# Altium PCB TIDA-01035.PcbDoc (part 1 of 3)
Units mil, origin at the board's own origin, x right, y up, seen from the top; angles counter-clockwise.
Board outline 3937.01 x 2952.76 mil, 4 copper layers (Top Layer, GND, PWR, Bottom Layer), stack 79.834 mil thick; 286 components, 165 nets, 861 pads, 352 vias.
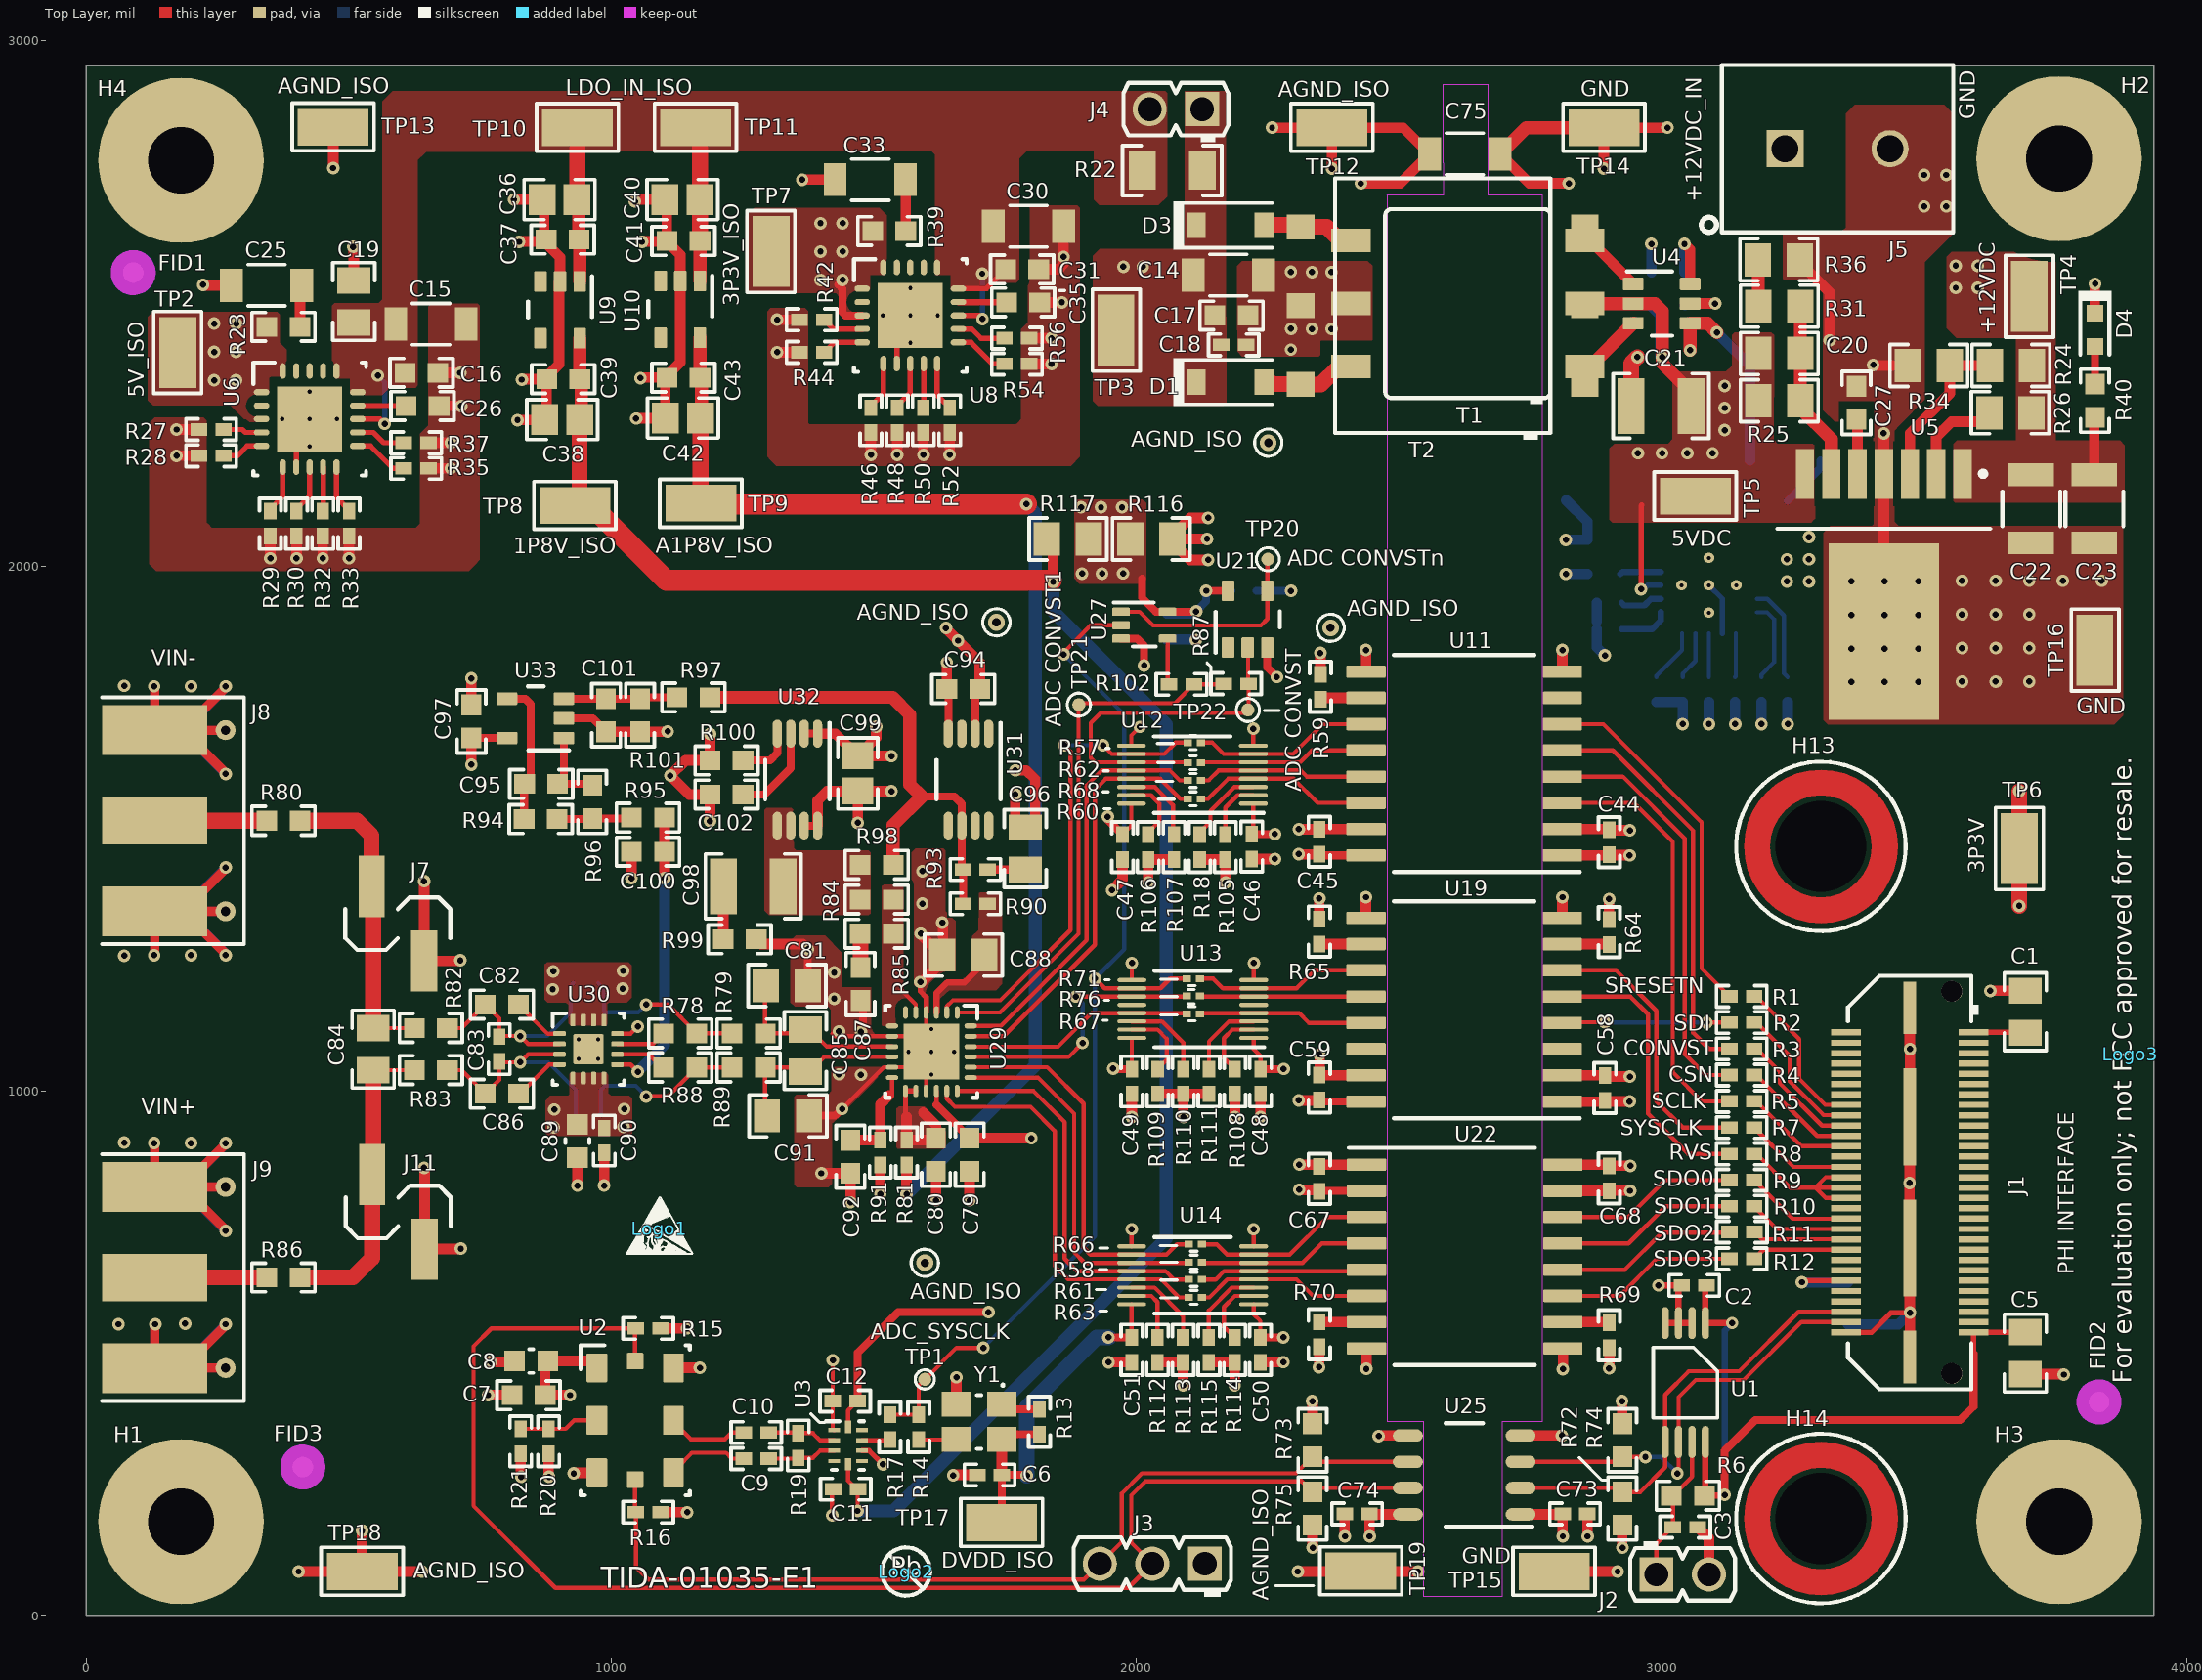
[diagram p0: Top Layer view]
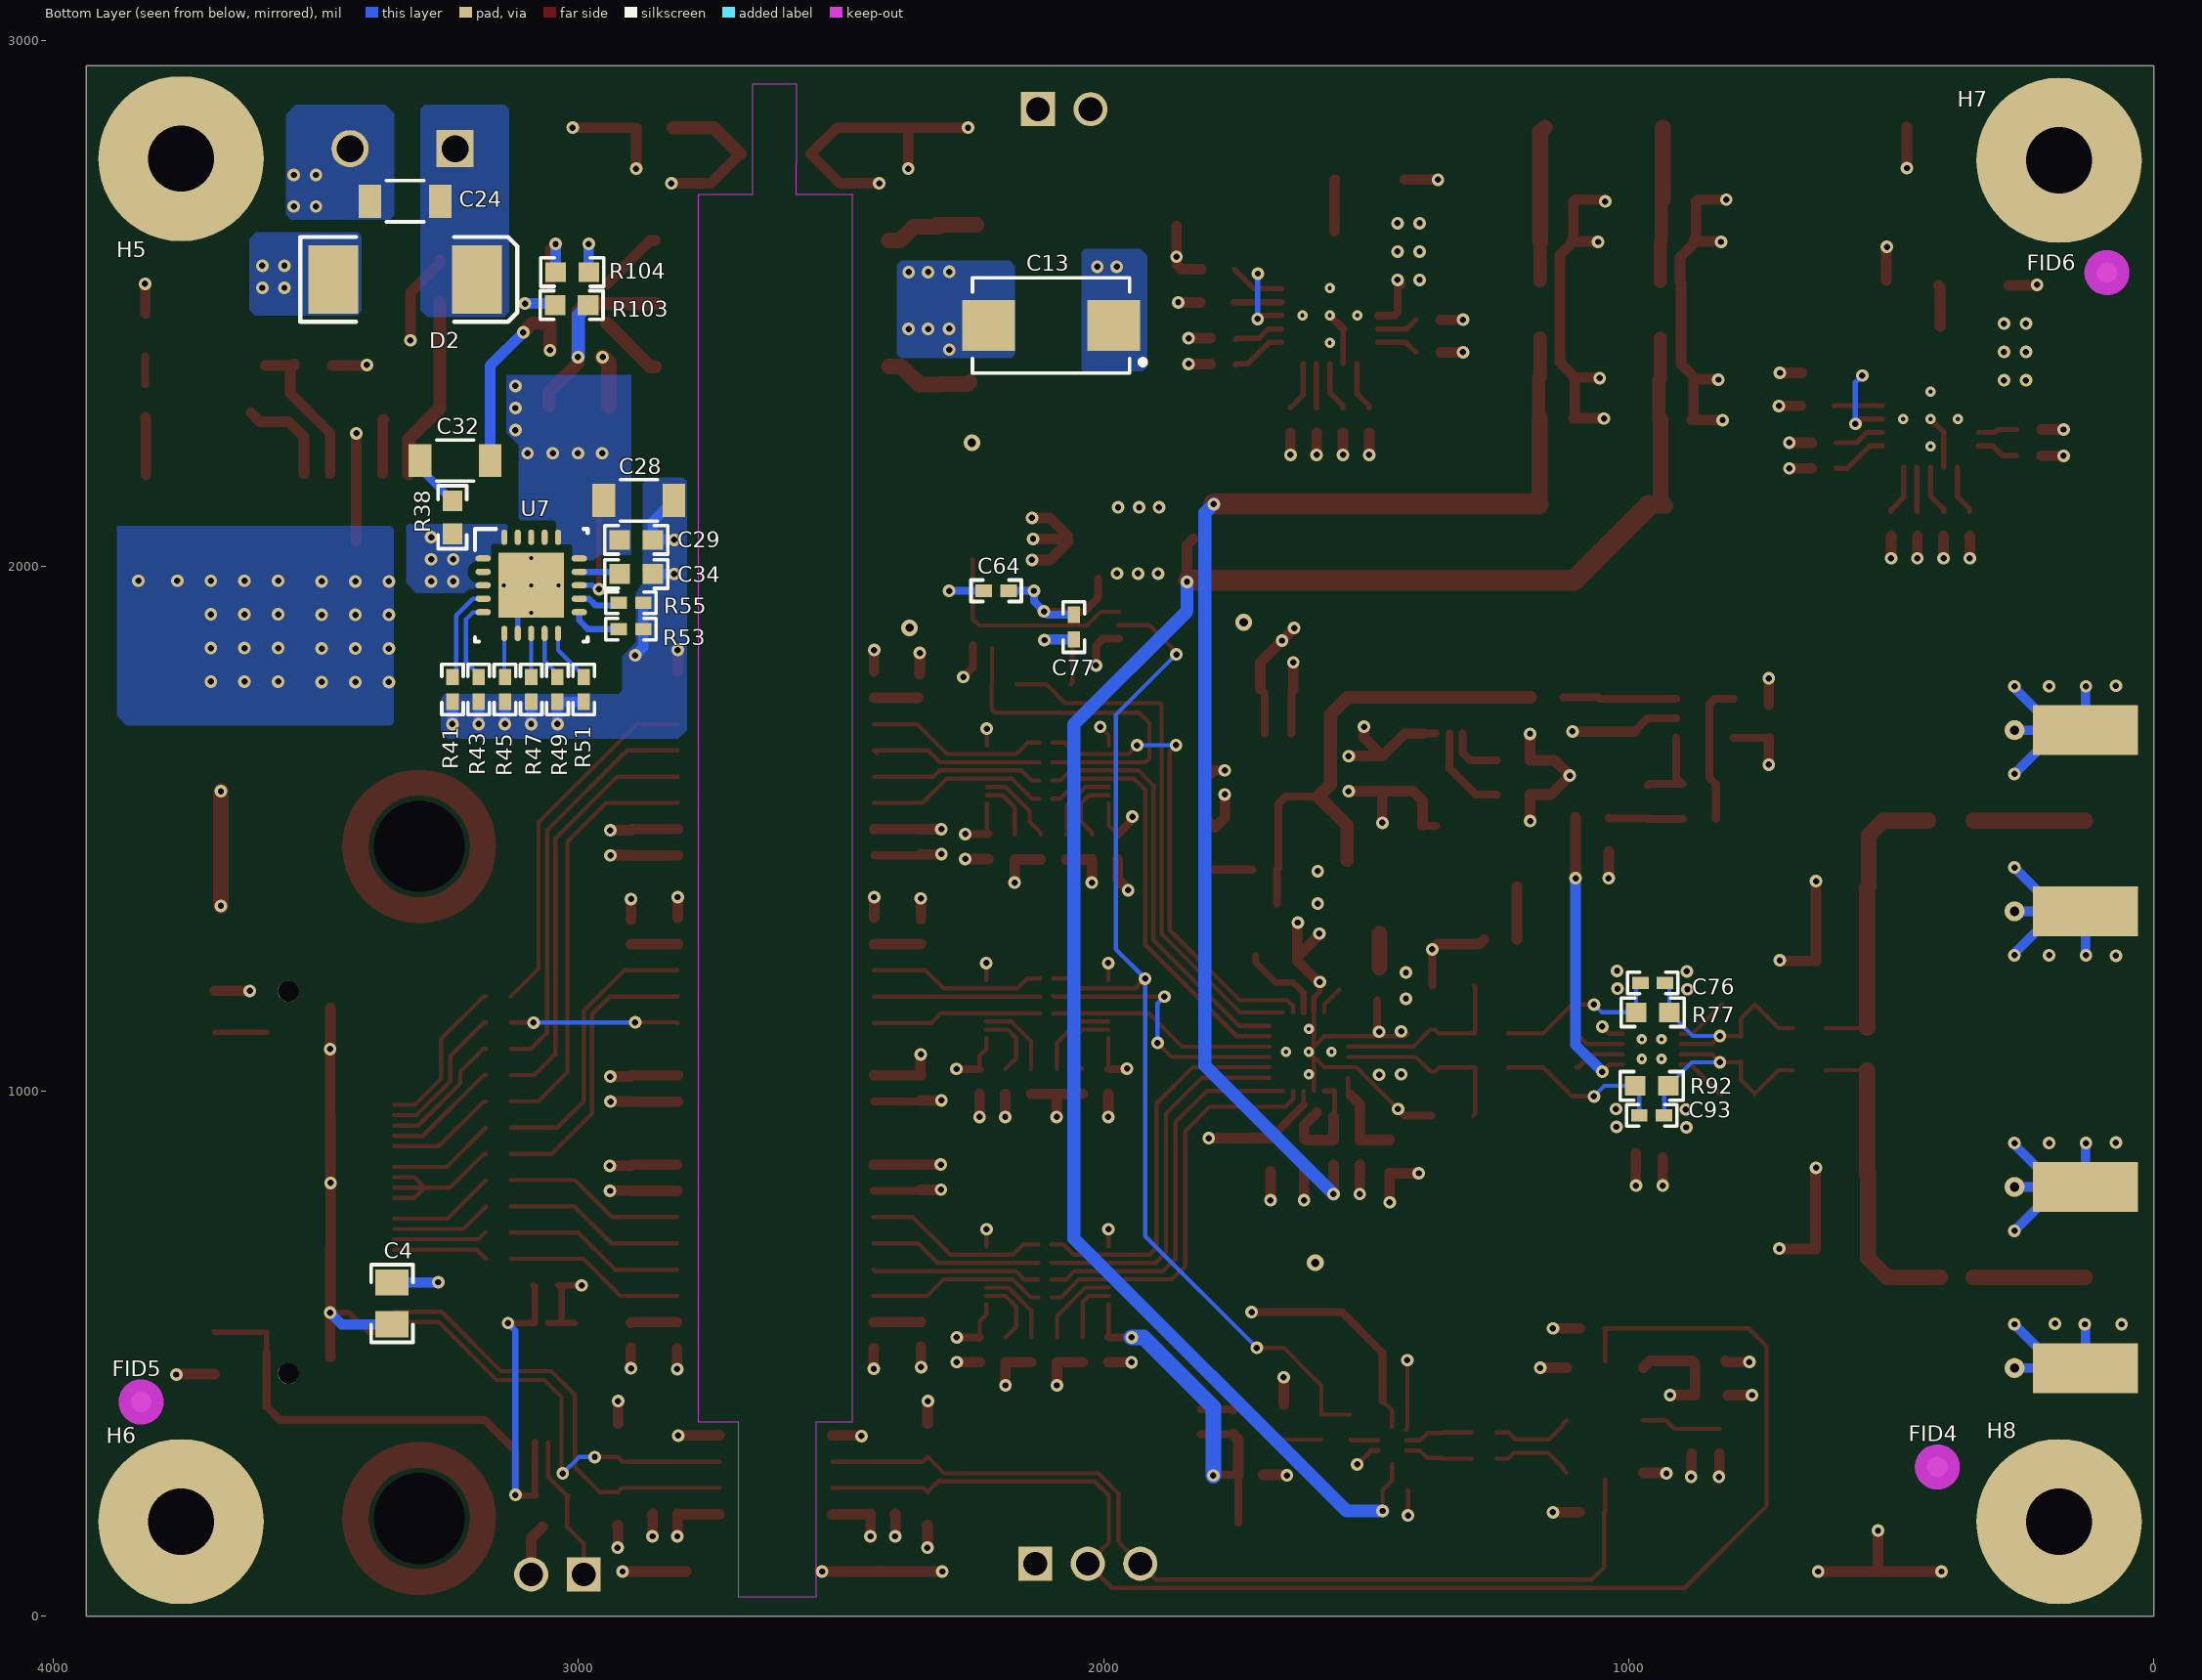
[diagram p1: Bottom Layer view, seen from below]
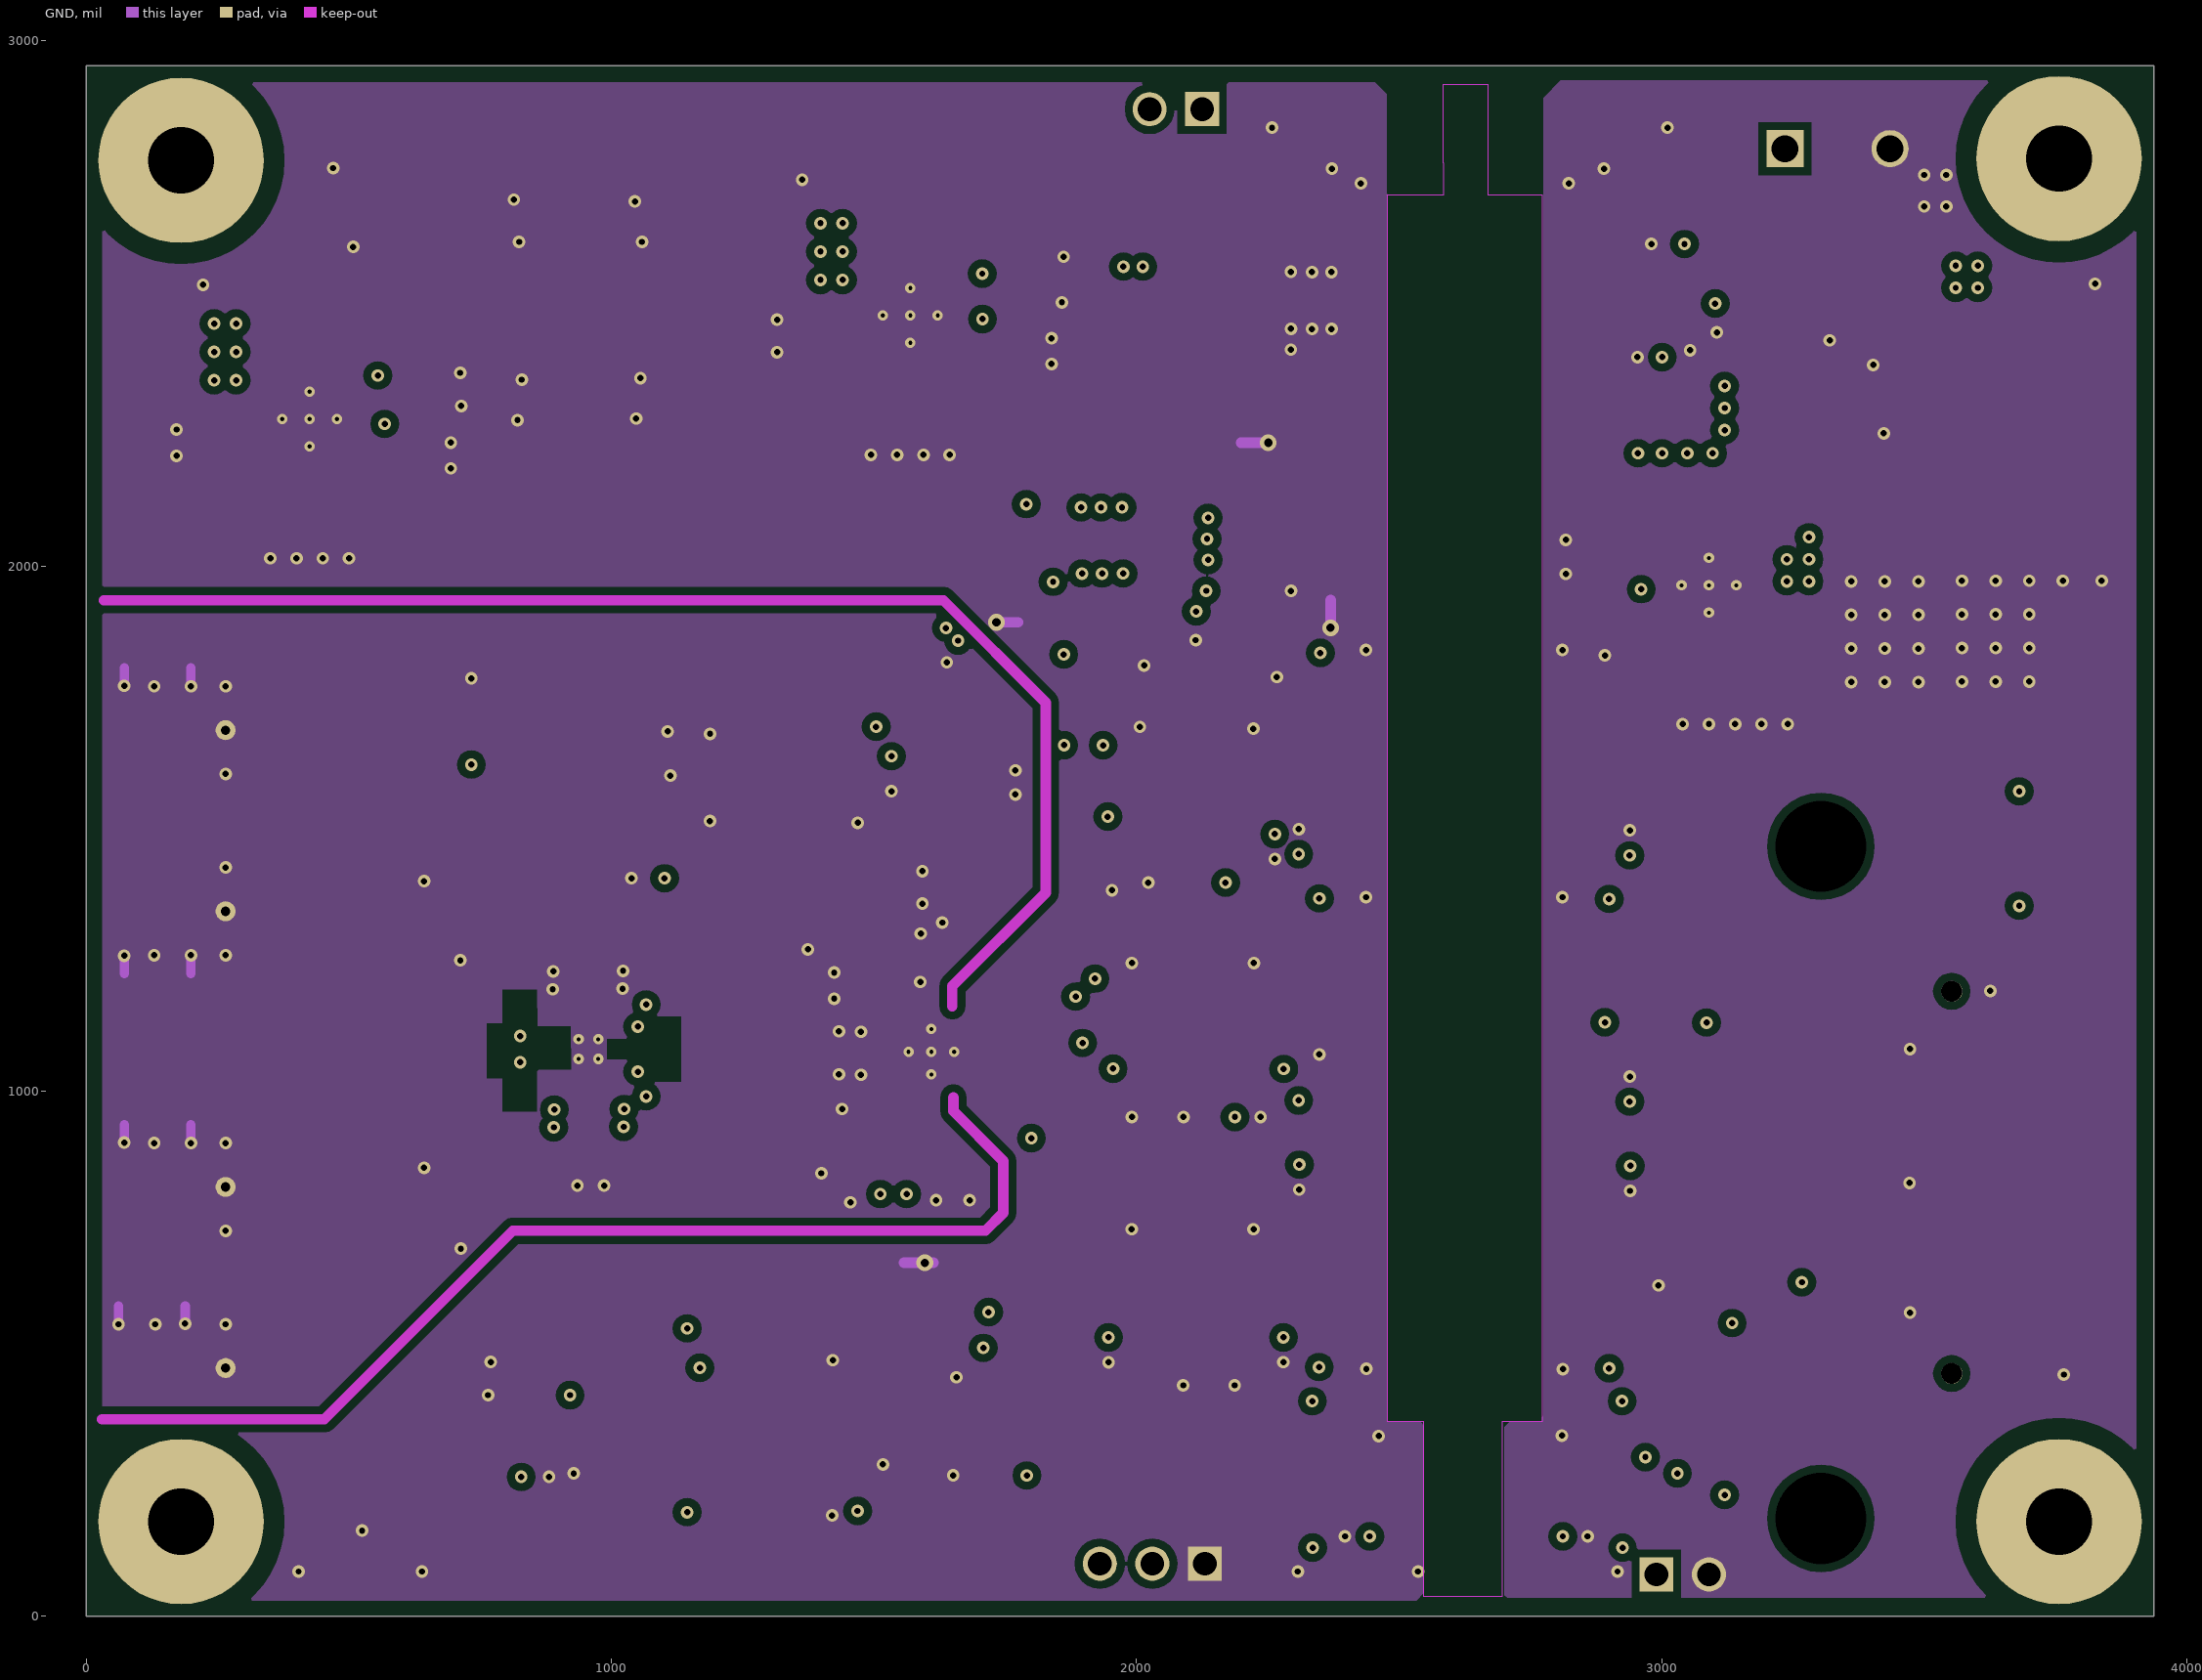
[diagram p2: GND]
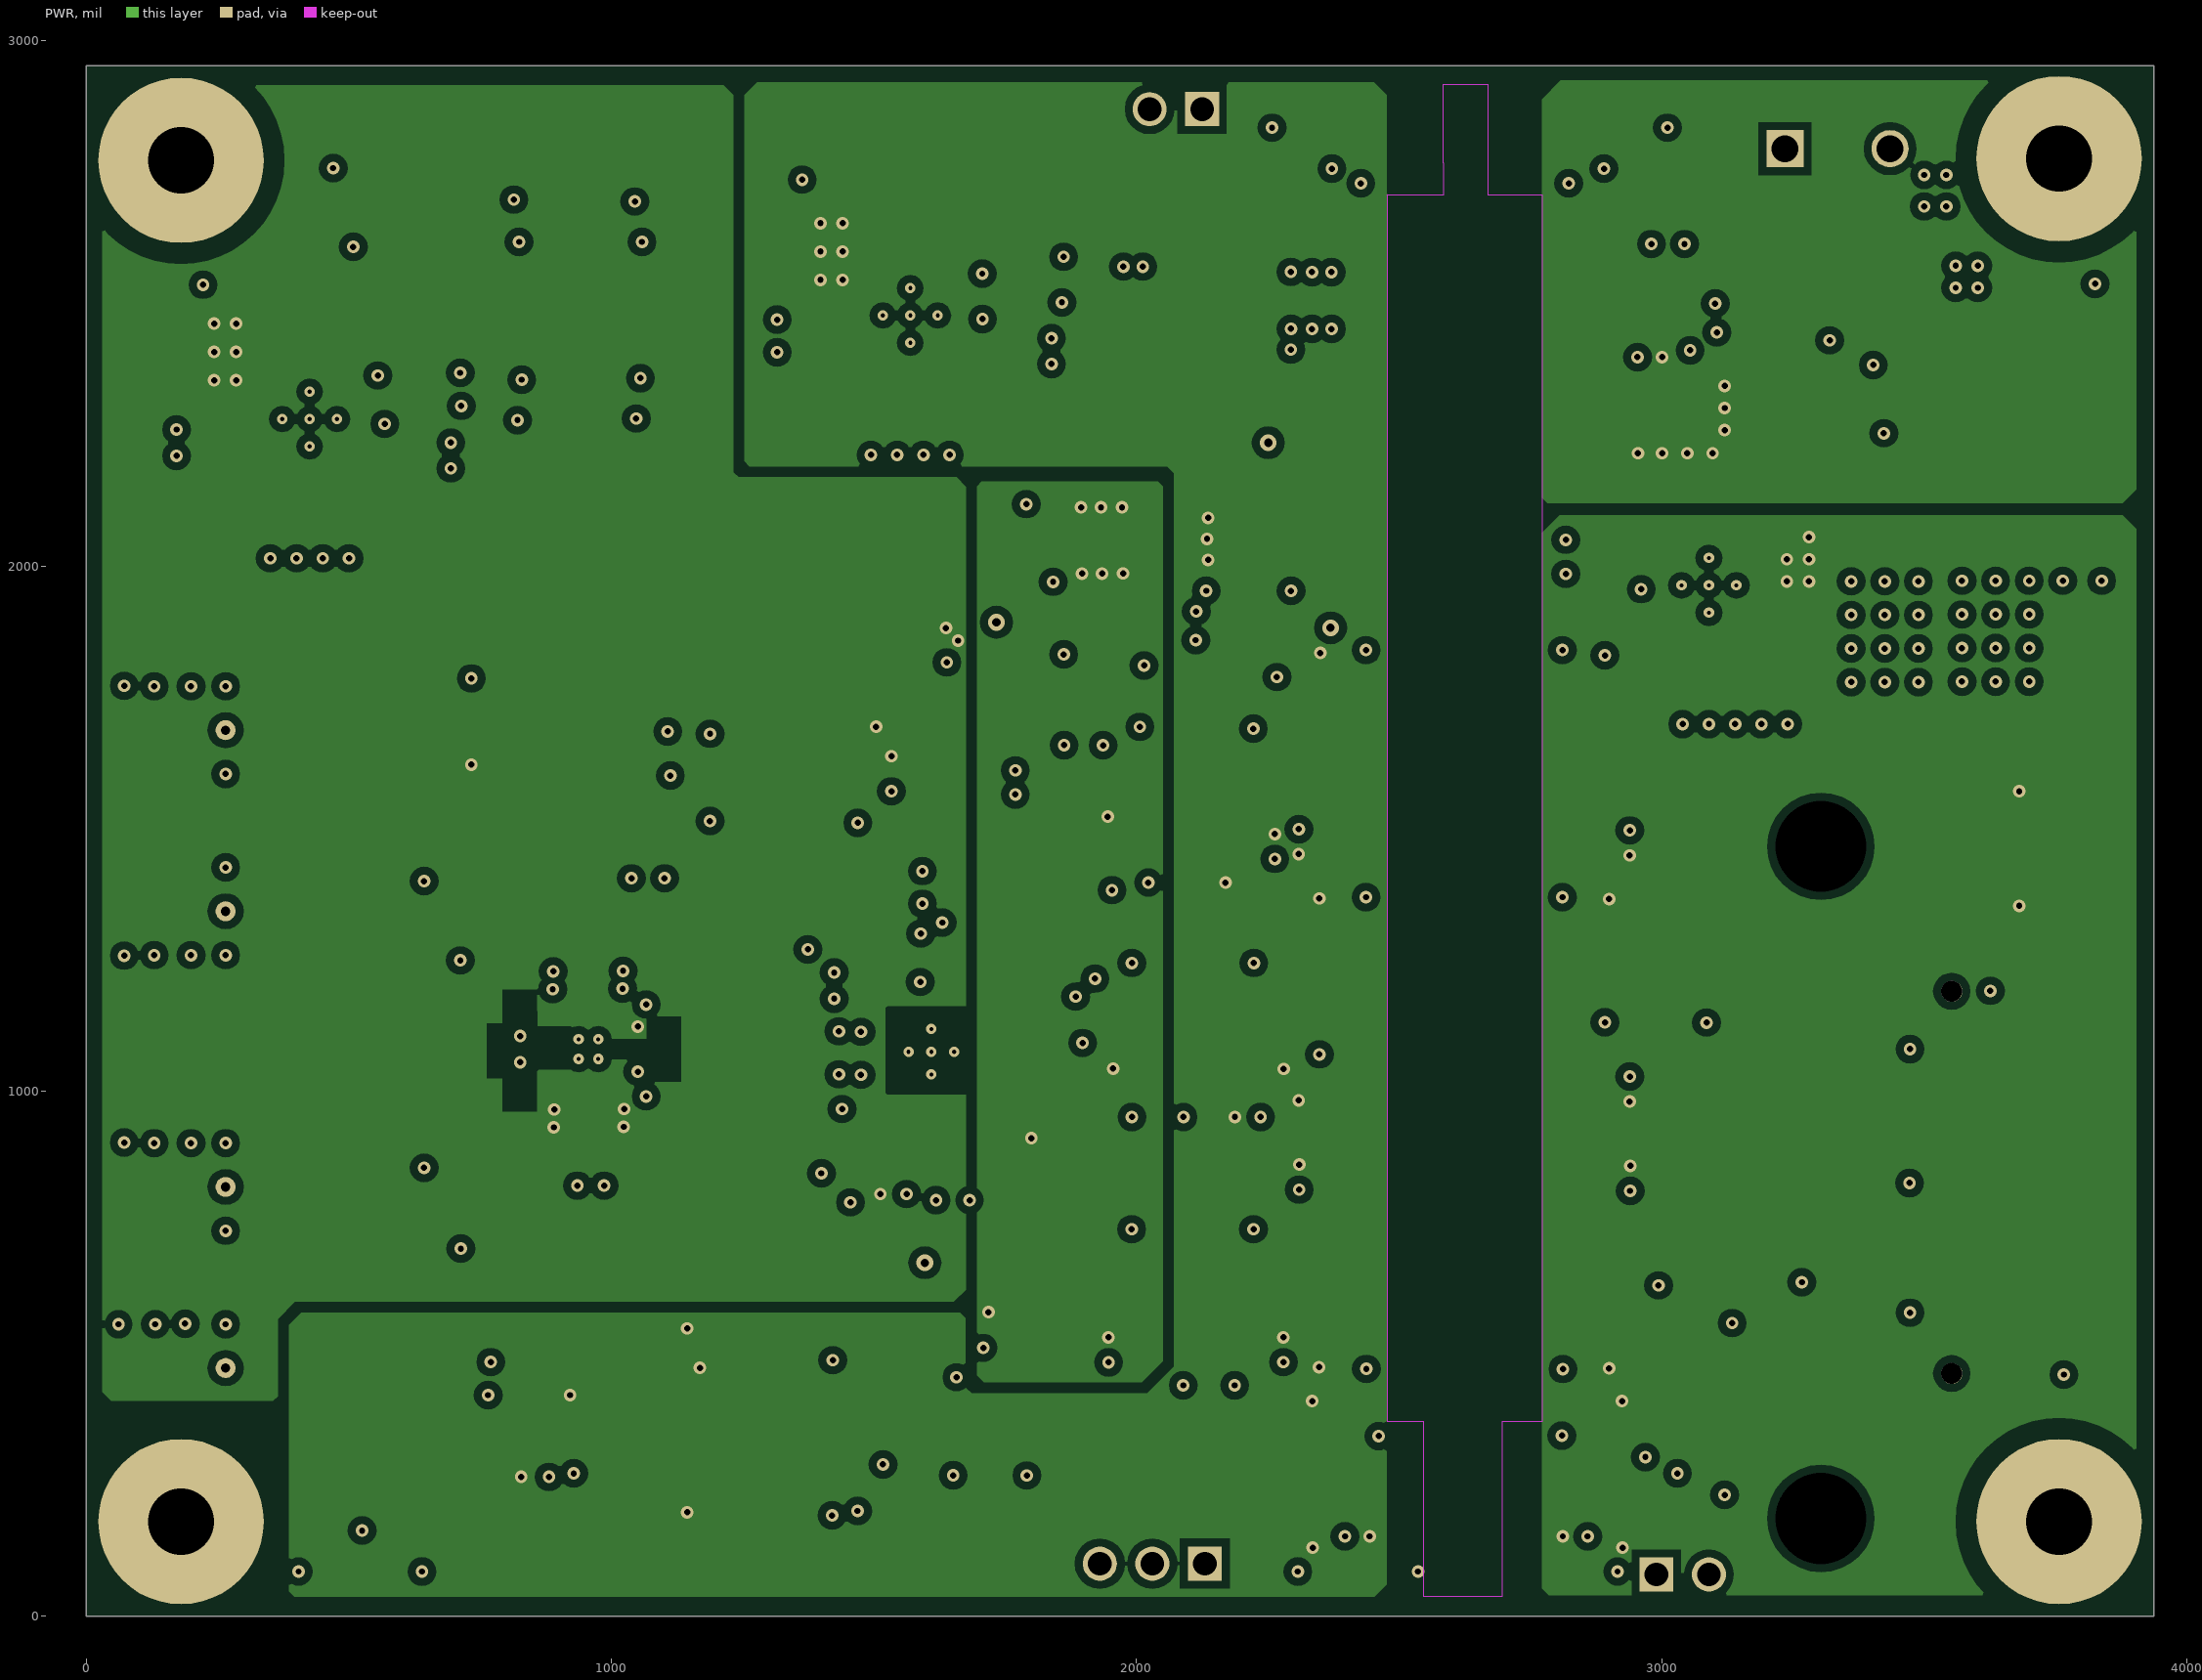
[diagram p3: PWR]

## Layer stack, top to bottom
Top Solder: solder mask 0.4, Solder Resist, Dk 3.5
Top Layer: signal copper 1.4
Dielectric1: core 59.2, FR-4, Dk 4.8
GND: signal copper 1.417
Dielectric 3: prepreg 5, Dk 4.2
PWR: signal copper 1.417
Dielectric 2: core 10, Dk 4.2
Bottom Layer: signal copper 1.4
Bottom Solder: solder mask 0.4, Solder Resist, Dk 3.5

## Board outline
0,0 0,2952.76 3937.01,2952.76 3937.01,0

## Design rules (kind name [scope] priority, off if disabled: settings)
AcuteAngle [All] p1: minimum=4.50000000000000E+0001 checktracksonly=FALSE
AssemblyTestPointUsage [All] p1: valid=2
Clearance Clearance_MTG_COPPER [InPadClass('MTG') vs InPoly] p1: gap=40
Clearance "Shape to Shape" [InPolygon vs InPolygon] p2: gap=20
Clearance "shape to all" [InPolygon] p3: gap=15
Clearance Clearance_Boardedge_poly [OnCopper and InPolygon vs IsKeepOut] p4: gap=20
Clearance Clearance_u [InPadClass('U31')] p5: gap=7.7
Clearance "Clearance_via_thr pin" [IsVia vs IsThruPin] p6: gap=8
Clearance "SMD to Via" [IsSMTPin vs IsVia] p7: gap=8
Clearance [All] p8: gap=7.5
DiffPairsRouting DiffPair_DiffPairsRouting [InDifferentialPair ('kan')] p1: maxlimit=16 minlimit=16 mostfreqgap=16 toplayer_minwidth=8 toplayer_maxwidth=8 toplayer_prefwidth=8 midlayer1_minwidth=8 midlayer1_maxwidth=8 midlayer1_prefwidth=8 midlayer2_minwidth=8 midlayer2_maxwidth=8 midlayer2_prefwidth=8 bottomlayer_minwidth=8 bottomlayer_maxwidth=8 bottomlayer_prefwidth=8 maxuncoupledlength=500
DiffPairsRouting [All] p2: maxlimit=16 minlimit=16 mostfreqgap=16 toplayer_minwidth=8 toplayer_maxwidth=8 toplayer_prefwidth=8 midlayer1_minwidth=8 midlayer1_maxwidth=8 midlayer1_prefwidth=8 midlayer2_minwidth=8 midlayer2_maxwidth=8 midlayer2_prefwidth=8 bottomlayer_minwidth=8 bottomlayer_maxwidth=8 bottomlayer_prefwidth=8 maxuncoupledlength=1000
FabricationTestPointUsage TestPointUsage [All] p1: valid=2 allowmultiple=FALSE
FabricationTestpoint Testpoint [All] p1: side=3 testpointundercomponent=TRUE minsize=40 maxsize=100 preferedsize=60 minholesize=0 maxholesize=40 preferedholesize=32 testpointgrid=1 allowsidetop=TRUE allowsidebottom=TRUE usegrid=TRUE gridtolerance=0.01
FanoutControl Fanout_LCC [IsLCC] p1: bgadir=Out bgaviamode=Centered fanoutstyle=Auto fanoutdirection=Alternating viagrid=1 // Fanout_LCC (Default Rule)
FanoutControl Fanout_BGA [IsBGA] p2: bgadir=Out bgaviamode=Centered fanoutstyle=Auto fanoutdirection=Alternating viagrid=1 // Fanout_BGA (Default Rule)
FanoutControl Fanout_Default [All] p4: bgadir=Out bgaviamode=Centered fanoutstyle=Auto fanoutdirection=Alternating viagrid=1 // Fanout_Default (Default Rule)
FanoutControl Fanout_Small [(CompPinCount < 5)] p5: bgadir=Out bgaviamode=Centered fanoutstyle=Auto fanoutdirection=OutThenIn viagrid=1 // Fanout_Small (Default Rule)
HoleSize [All] p1: absolutevalues=TRUE maxlimit=251 minlimit=7 maxpercent=80.000 minpercent=20.000
MatchedLengths DiffPair_MatchedLengths [InDifferentialPair ('kan')] p1: tolerance=1000 checknetsindiffpair=TRUE checkdiffpairvsdiffpair=FALSE checkxsignals=FALSE checkothers=FALSE
MatchedLengths DiffPair_MatchedLengths_1 [InDifferentialPair ('kan')] p2: tolerance=1000 checknetsindiffpair=TRUE checkdiffpairvsdiffpair=FALSE checkxsignals=FALSE checkothers=FALSE
MinimumAnnularRing [All] p1: minimumring=5
MinimumAnnularRing MinimumAnnularRing_ThermalPadVias [IsVia and InAnyComponent] p2: minimumring=5.91
MinimumSolderMaskSliver MinimumSolderMaskSliver_Logo [InComponentClass('Logo') vs InComponentClass('Logo')] p1: minsoldermaskwidth=0.7
MinimumSolderMaskSliver [All] p2: minsoldermaskwidth=3.94
PlaneClearance [All] p1: clearance=15
PlaneConnect [All] p1: planeconnectstyle=Direct reliefexpansion=10 reliefentries=4 reliefconductorwidth=10 reliefairgap=10
PolygonConnect [All] p1: connectstyle=Direct reliefconductorwidth=10 reliefentries=4 polygonreliefangle="90 Angle" airgapwidth=10
RoutingVias RoutingVias_power [InNetClass('POWER')] p1: holewidth=16 width=32 viastyle="Through Hole" minholewidth=7.87 minwidth=19.68 maxholewidth=16 maxwidth=32
RoutingVias ThermalPadVias [IsVia and InAnyComponent] p2: holewidth=8 width=20 viastyle="Through Hole" minholewidth=7.87 minwidth=19 maxholewidth=12 maxwidth=24
RoutingVias [All] p3: holewidth=12 width=24 viastyle="Through Hole" minholewidth=7.87 minwidth=19.68 maxholewidth=16 maxwidth=32
SMDToCorner [All] p1: distance=30000
SilkToSilkClearance [All] p1: silktosilkclearance=5
SilkToSolderMaskClearance SilkscreenOverComponentPads [IsPad] p1: minsilkscreentomaskgap=5 clearancetoexposedcopper=TRUE
SolderMaskExpansion [All] p1: expansion=3
Width Width_power [InNetClass('pwr')] p1: maxlimit=200 minlimit=8 preferedwidth=20
Width [All] p2: maxlimit=100 minlimit=6 preferedwidth=8 checkconnectedcopper=TRUE
16 further rules are at their usual default settings.

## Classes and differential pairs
component class "Mounting Holes": H1 H2 H3 H4
pad class MTG: H1-1 H2-1 H3-1 H4-1 H5-0 H6-0 H7-0 H8-0
component class Header: J2 J3 J4 J7 J11
component class AssemblyNote: ZZ1 ZZ2 ZZ3
pad class U31: J1-1 J1-2 J1-3 J1-4 J1-5 J1-6 J1-7 J1-8 J1-9 J1-10 J1-11 J1-12 J1-13 J1-14 J1-15 J1-16 J1-17 J1-18 J1-19 J1-20 J1-21 J1-22 J1-23 J1-24 J1-25 J1-26 J1-27 J1-28 J1-29 J1-30 J1-31 J1-32 J1-33 J1-34 J1-35 J1-36 J1-37 J1-38 J1-39 J1-40 J1-41 J1-42 J1-43 J1-44 J1-45 J1-46 J1-47 J1-48 J1-49 J1-50 J1-51 J1-52 J1-53 J1-54 J1-55 J1-56 J1-57 J1-58 J1-59 J1-60 J1-MH1 J1-MH2 J1-MP1 J1-MP2 J1-MP3 J1-MP4 U13-1 U13-2 U13-3 U13-4 U13-5 U13-6 U13-7 U13-8 U13-9 U13-10 U13-11 U13-12 U13-13 U13-14 U13-15 U13-16 U14-1 U14-2 U14-3 U14-4 U14-5 U14-6 U14-7 U14-8 U14-9 U14-10 U14-11 U14-12 U14-13 U14-14 U14-15 U14-16 U31-1 U31-2 U31-3 U31-4 U31-5 U31-6 U31-7 U31-8 U32-2 U32-3 U32-4 U32-5 U32-6 U32-7 U32-8 U33-1 U33-2 U33-3 U33-4 U33-5
component class TIDA-01035_Hardware: FID1 FID2 FID3 FID4 FID5 FID6 H1 H2 H3 H4 H5 H6 H7 H8 H13 H14 Logo1 Logo2 Logo3 ZZ1 ZZ2 ZZ3
component class FiducialMark: FID1 FID2 FID3 FID4 FID5 FID6
component class TIDA-01035_ADC1: C64 C76 C77 C79 C80 C81 C82 C83 C84 C85 C86 C87 C88 C89 C90 C91 C92 C93 C94 C95 C96 C97 C98 C99 C100 C101 C102 J7 J8 J9 J11 R77 R78 R79 R80 R81 R82 R83 R84 R85 R86 R87 R88 R89 R90 R91 R92 R93 R94 R95 R96 R97 R98 R99 R100 R101 R102 R116 R117 TP20 TP21 TP22 U21 U27 U29 U30 U31 U32 U33
component class TIDA-01035_CONNECTOR: C1 C2 C3 C4 C5 C6 C7 C8 C9 C10 C11 C12 J1 J2 J3 R1 R2 R3 R4 R5 R6 R7 R8 R9 R10 R11 R12 R13 R14 R15 R16 R17 R19 R20 R21 TP1 U1 U2 U3 Y1
component class TIDA-01035_DATA_ISOLATION: C44 C45 C46 C47 C48 C49 C50 C51 C58 C59 C67 C68 C73 C74 C75 R18 R57 R58 R59 R60 R61 R62 R63 R64 R65 R66 R67 R68 R69 R70 R71 R72 R73 R74 R75 R76 R105 R106 R107 R108 R109 R110 R111 R112 R113 R114 R115 TP12 TP13 TP14 TP15 TP16 TP17 TP18 TP19 U11 U12 U13 U14 U19 U22 U25
component class TIDA-01035_POWER_ISOLATION: C13 C14 C15 C16 C17 C18 C19 C20 C21 C22 C23 C24 C25 C26 C27 C28 C29 C30 C31 C32 C33 C34 C35 C36 C37 C38 C39 C40 C41 C42 C43 D1 D2 D3 D4 J4 J5 R22 R23 R24 R25 R26 R27 R28 R29 R30 R31 R32 R33 R34 R35 R36 R37 R38 R39 R40 R41 R42 R43 R44 R45 R46 R47 R48 R49 R50 R51 R52 R53 R54 R55 R56 R103 R104 T1 T2 TP2 TP3 TP4 TP5 TP6 TP7 TP8 TP9 TP10 TP11 U4 U5 U6 U7 U8 U9 U10
differential pair BCLK: +BCLK_P -BCLK_N

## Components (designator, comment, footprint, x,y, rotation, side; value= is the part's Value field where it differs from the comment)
C1 "GRM21BR71A106KE51L" 0805_HV 3692.5,1151.05 r90 top
C2 "GRM155R71C104KA88D" 0402 3062,630 r0 top
C3 "GRM155R71C104KA88D" 0402 3045,169.5 r180 top
C4 "GRM21BR71A106KE51L" 0805_HV 3355,595.62 r270 bottom
C5 "GRM21BR71A106KE51L" 0805_HV 3692.5,501.05 r270 top
C6 "GRM155R71C104KA88D" 0402 1720,269 r180 top
C7 "C0603C104J3RACTU" 0603 842,421 r180 top
C8 "ZRB18AD71A106KE01L" 0603_120 847,486 r180 top
C9 "GRM155R61E104KA87D" 0402 1275.51,300 r0 top
C10 "GRM155R61E104KA87D" 0402 1275.51,350 r0 top
C11 "GRM155R71C104KA88D" 0402 1446,242 r180 top
C12 "GRM155R71C104KA88D" 0402 1445,410 r180 top
C13 "TPME107K020R0035" 7343-43 2099.79,2458.35 r0 bottom
C14 "C3216X7R1E106M160AE" 1206_190 2174.79,2554.35 r0 top
C15 "C3216X5R1E476M160AC" 1206_190 656.07,2460.86 r0 top
C16 "GRM1885C1H102FA01J" 0603 638.06,2368.06 r0 top
C17 "GRM188R71E105KA12D" 0603 2180.79,2477.35 r0 top
C18 "GRM155R71C104KA88D" 0402 2184.79,2421.35 r180 top
C19 "GRM21BR71A106KE51L" 0805_HV 509,2504 r90 top
C20 "08055C223KAT2A" 0805_HV 3224,2405 r0 top
C21 "C3225X5R1A226M230AA" 1210 2999,2305 r180 top
C22 "C1210C106K5RACTU" 1210_280 3704,2109 r270 top
C23 "C1210C106K5RACTU" 1210_280 3824,2109 r270 top
C24 "C3216X7R1E106M160AE" 1206_190 3330,2695 r0 bottom
C25 "C3216X5R1E476M160AC" 1206_190 343.07,2534.86 r180 top
C26 "GRM188R71E105KA12D" 0603 640.06,2305.06 r180 top
C27 "C0603C103J5RACTU" 0603 3371,2311 r90 top
C28 "C3216X5R1E476M160AC" 1206_190 2885,2125 r180 bottom
C29 "GRM1885C1H102FA01J" 0603 2890,2050 r180 bottom
C30 "C3216X5R1E476M160AC" 1206_190 1794,2647.27 r0 top
C31 "GRM1885C1H102FA01J" 0603 1782,2565.27 r0 top
C32 "C3216X5R1E476M160AC" 1206_190 3235,2201 r180 bottom
C33 "C3216X5R1E476M160AC" 1206_190 1493,2736 r180 top
C34 "GRM188R71E105KA12D" 0603 2890,1985 r0 bottom
C35 "GRM188R71E105KA12D" 0603 1784,2502.27 r180 top
C36 "08055C105KAT2A" 0805 901,2698 r180 top
C37 "C0603C104K5RACTU" 0603 907,2622 r180 top
C38 "0805YD106MAT2A" 0805 906,2279 r180 top
C39 "C0603C104K5RACTU" 0603 908,2356 r180 top
C40 "08055C105KAT2A" 0805 1135,2698 r180 top
C41 "C0603C104K5RACTU" 0603 1137,2619 r180 top
C42 "0805YD106MAT2A" 0805 1136,2282 r180 top
C43 "C0603C104K5RACTU" 0603 1137,2359 r180 top
C44 "GRM155R71C104KA88D" 0402 2900,1474 r270 top
C45 "GRM155R71C104KA88D" 0402 2348,1475 r90 top
C46 "GRM155R71C104KA88D" 0402 2219.18,1465.77 r270 top
C47 "GRM155R71C104KA88D" 0402 1973.18,1464.77 r270 top
C48 "GRM155R71C104KA88D" 0402 2236.04,1018.4 r270 top
C49 "GRM155R71C104KA88D" 0402 1991.04,1018.4 r270 top
C50 "GRM155R71C104KA88D" 0402 2235.68,507.27 r270 top
C51 "GRM155R71C104KA88D" 0402 1990.68,507.27 r270 top
C58 "GRM155R71C104KA88D" 0402 2892,1006 r270 top
C59 "GRM155R71C104KA88D" 0402 2348,1007 r90 top
C64 "GRM155R71C104KA88D" 0402 2204.58,1952.91 r180 bottom
C67 "GRM155R71C104KA88D" 0402 2348,833 r90 top
C68 "GRM155R71C104KA88D" 0402 2900,834 r270 top
C73 "GRM155R71C104KA88D" 0402 2835,195 r180 top
C74 "GRM155R71C104KA88D" 0402 2420,195 r180 top
C75 "202R18W102KV4E" 1206_190 2625,2785 r0 top
C76 "885012005061" 0402 954,1206 r180 bottom
C77 "GRM155R71C104KA88D" 0402 2056.58,1883.91 r90 bottom
C79 "GRM188R71E105KA12D" 0603 1682,879 r90 top
C80 "GRM188R71E105KA12D" 0603 1618,879 r270 top
C81 "GRM2165C2A471JA01D" 0805_HV 1334,1201 r0 top
C82 "GRM1885C1H102FA01J" 0603 791,1165 r180 top
C83 "885012005061" 0402 786,1080 r270 top
C84 "C0805C103F1GACTU" 0805_HV 546,1080 r90 top
C85 "C0805C102J1GACTU" 0805_HV 1369,1077 r270 top
C86 "GRM1885C1H102FA01J" 0603 791,995 r180 top
C87 "GRM188R60J226MEA0J" 0603 1474,1204 r270 top
C88 "GRM21BR71A106KE51L" 0805_HV 1670,1259 r180 top
C89 "ZRB18AD71A106KE01L" 0603_120 935,905 r270 top
C90 "GRM155R71C104KA88D" 0402 986,906 r90 top
C91 "GRM2165C2A471JA01D" 0805_HV 1336,953 r0 top
C92 "GRM188R71E105KA12D" 0603 1455,875 r270 top
C93 "885012005061" 0402 956,954 r180 bottom
C94 "GRM188R71E105KA12D" 0603 1670,1766 r180 top
C95 "GRM188R71E105KA12D" 0603 866,1585 r180 top
C96 "GRM21BR71A106KE51L" 0805_HV 1788,1462 r90 top
C97 "C0603C104J3RACTU" 0603 733,1704 r270 top
C98 "GRM32ER71A476KE15L" 1210 1270,1390 r0 top
C99 "GRM21BR71A106KE51L" 0805 1469,1605 r90 top
C100 "GRM188R71E105KA12D" 0603 1069.5,1456 r180 top
C101 "GRM188R71E105KA12D" 0603 989.5,1716 r270 top
C102 "GRM188R71A105KA61D" 0603 1219.06,1564.94 r180 top
D1 "MBR0520LT1G" SOD-123 2178,2350.35 r0 top
D2 "MBRS4201T3G" SMC 3330,2546 r180 bottom
D3 "MBR0520LT1G" SOD-123 2178,2649 r0 top
D4 "150060RS75000" WL-SMCW_RED 3825,2450 r270 top
FID1 "Fiducial" Fiducial10-20 89,2559 r180 top
FID2 "Fiducial" Fiducial10-20 3833,408 r180 top
FID3 "Fiducial" Fiducial10-20 412,284 r180 top
FID4 "Fiducial" Fiducial10-20 412,284 r0 bottom
FID5 "Fiducial" Fiducial10-20 3833,408 r0 bottom
FID6 "Fiducial" Fiducial10-20 89,2559 r0 bottom
H1 "9330" "NY PMS 440 0025 PH" 180,180 r0 top
H2 "9330" "NY PMS 440 0025 PH" 3757.01,2775.91 r0 top
H3 "9330" "NY PMS 440 0025 PH" 3757.01,180 r0 top
H4 "9330" "NY PMS 440 0025 PH" 180,2772.76 r0 top
H5 "1902C" Keystone_1902C 3757.01,2775.91 r180 bottom
H6 "1902C" Keystone_1902C 3757.01,180 r180 bottom
H7 "1902C" Keystone_1902C 180,2772.76 r180 bottom
H8 "1902C" Keystone_1902C 180,180 r180 bottom
H13 "9774050360R" Wurth_WA-SMSI 3303.24,1466.05 r0 top locked
H14 "9774050360R" Wurth_WA-SMSI 3303.24,186.05 r0 top locked
J1 "QTH-030-03-L-D-A" SAMTEC_QTH-030-01-X-D-A 3472.5,826.05 r270 top
J2 "61300211121" WURTH_61300211121 3040,79.5 r0 top
J3 "61300311121" WURTH_61300311121 2030,100 r180 top
J4 "61300211121" WURTH_61300211121 2074.79,2870.35 r180 top
J5 "8718" 691213510002 3335,2795 r0 top
J7 "0878980204" Molex_87898-0204 593,1319 r180 top
J8 "142-0701-801" JOHNSON_142-0701-801#1 130,1515 r90 top locked
J9 "142-0701-801" JOHNSON_142-0701-801#2 130,645 r90 top locked
J11 "0878980204" Molex_87898-0204 594,770 r180 top
Logo1 "ESD Susceptible" ESD_Overlay_small 1091,738 r0 top
Logo2 "Pb-Free Symbol" Pb-Free_Overlay_Small 1561,85 r0 top
Logo3 "FCC disclaimer" FCC_disclaimer 3893,1070 r90 top
R1 "ERJ-2GE0R00X" 0402 3152.5,1180.55 r0 top
R2 "ERJ-2GE0R00X" 0402 3152.5,1130.55 r0 top
R3 "ERJ-2GE0R00X" 0402 3152.5,1080.55 r0 top
R4 "ERJ-2GE0R00X" 0402 3152.5,1030.55 r0 top
R5 "ERJ-2GE0R00X" 0402 3152.5,980.55 r0 top
R6 "CRCW060310K0FKEA" 0603 3050,229.5 r0 top
R7 "ERJ-2GE0R00X" 0402 3152.5,930.55 r0 top
R8 "ERJ-2GE0R00X" 0402 3152.5,880.55 r0 top
R9 "ERJ-2GE0R00X" 0402 3152.5,830.55 r0 top
R10 "ERJ-2GE0R00X" 0402 3152.5,780.55 r0 top
R11 "ERJ-2GE0R00X" 0402 3153,732 r0 top
R12 "ERJ-2GE0R00X" 0402 3152.5,680.55 r0 top
R13 "CRCW040233R0JNED" 0402 1815,370 r270 top
R14 "CRCW040233R0JNED" 0402 1585,360 r90 top
R15 "CRCW04024K70JNED" 0402 1070,548 r0 top
R16 "CRCW04024K70JNED" 0402 1070,198 r0 top
R17 "CRCW040233R0JNED" 0402 1530,360 r90 top
R18 "ERJ-2RKF1002X" 0402 2120.18,1464.77 r270 top
R19 "RC0402FR-07100RL" 0402 1355.51,325 r270 top
R20 "CRCW04024K70JNED" 0402 880,333 r90 top
R21 "CRCW04024K70JNED" 0402 827,333 r90 top
R22 "CRCW12060000Z0EA" 1206 2067.79,2753.35 r180 top
R23 "ERJ-3RSFR10V" 0603 375.07,2455.86 r180 top
R24 "ERJ-6ENF1183V" 0805_HV 3665,2382 r0 top
R25 "RC0805FR-075K62L" 0805_HV 3224,2315 r180 top
R26 "CRCW0805249KFKEA" 0805_HV 3664,2292 r0 top
R27 "ERJ-2GE0R00X" 0402 237.44,2260.06 r0 top
R28 "ERJ-2GE0R00X" 0402 237.44,2210.06 r0 top
R29 "ERJ-2GE0R00X" 0402 350.06,2080.68 r90 top
R30 "ERJ-2GE0R00X" 0402 400.06,2080.68 r90 top
R31 "RR1220P-5490-D-M" 0805_HV 3224,2495 r0 top
R32 "ERJ-2GE0R00X" 0402 450.06,2080.68 r90 top
R33 "ERJ-2GE0R00X" 0402 500.06,2080.68 r90 top
R34 "CRCW080520K5FKEA" 0805_HV 3509,2382 r0 top
R35 "ERJ-2GE0R00X" 0402 628.06,2186.06 r180 top
R36 "RR1220P-3920-D-M" 0805_HV 3223.21,2583.35 r180 top
R37 "ERJ-2GE0R00X" 0402 628.06,2235.06 r180 top
R38 "ERJ-3RSFR10V" 0603 3240,2093 r270 bottom
R39 "ERJ-3RSFR10V" 0603 1529,2638 r180 top
R40 "CRCW06031K20JNEA" 0603 3825,2315 r270 top
R41 "ERJ-2GE0R00X" 0402 3240,1765 r90 bottom
R42 "ERJ-2GE0R00X" 0402 1381.38,2469.27 r0 top
R43 "ERJ-2GE0R00X" 0402 3190,1765 r90 bottom
R44 "ERJ-2GE0R00X" 0402 1381.38,2407.27 r0 top
R45 "ERJ-2GE0R00X" 0402 3140,1765 r90 bottom
R46 "ERJ-2GE0R00X" 0402 1494,2277.89 r90 top
R47 "ERJ-2GE0R00X" 0402 3090,1765 r90 bottom
R48 "ERJ-2GE0R00X" 0402 1544,2277.89 r90 top
R49 "ERJ-2GE0R00X" 0402 3040,1765 r90 bottom
R50 "ERJ-2GE0R00X" 0402 1594,2277.89 r90 top
R51 "ERJ-2GE0R00X" 0402 2990,1765 r90 bottom
R52 "ERJ-2GE0R00X" 0402 1644,2277.89 r90 top
R53 "ERJ-2GE0R00X" 0402 2900,1880 r0 bottom
R54 "ERJ-2GE0R00X" 0402 1772,2385 r180 top
R55 "ERJ-2GE0R00X" 0402 2900,1930 r0 bottom
R56 "ERJ-2GE0R00X" 0402 1772,2434 r180 top
R57 "ERJ-1GN0R00C" 0201 2110.18,1663.77 r180 top
R58 "ERJ-1GN0R00C" 0201 2111.68,674.27 r180 top
R59 "ERJ-2RKF1002X" 0402 2350,1770 r90 top
R60 "ERJ-1GN0R00C" 0201 2110.18,1556.77 r180 top
R61 "ERJ-1GN0R00C" 0201 2111.68,641.27 r180 top
R62 "ERJ-1GN0R00C" 0201 2110.18,1625.77 r180 top
R63 "ERJ-1GN0R00C" 0201 2111.68,607.27 r180 top
R64 "ERJ-2RKF1002X" 0402 2900,1303 r270 top
R65 "ERJ-2RKF1002X" 0402 2348,1304 r90 top
R66 "ERJ-1GN0R00C" 0201 2111.68,708.27 r180 top
R67 "ERJ-1GN0R00C" 0201 2108.04,1147.4 r180 top
R68 "ERJ-1GN0R00C" 0201 2110.18,1591.77 r180 top
R69 "ERJ-2RKF1002X" 0402 2900,535 r270 top
R70 "ERJ-2RKF1002X" 0402 2348,537 r90 top
R71 "ERJ-1GN0R00C" 0201 2108.04,1214.4 r180 top
R72 "CRCW06031K50JNEA" 0603 2925,205 r270 top
R73 "CRCW06031K50JNEA" 0603 2335,335 r90 top
R74 "CRCW06031K50JNEA" 0603 2925,335 r90 top
R75 "CRCW06031K50JNEA" 0603 2335,205 r270 top
R76 "ERJ-1GN0R00C" 0201 2108.04,1181.4 r180 top
R77 "RG1608P-102-B-T5" 0603 954,1150 r0 bottom
R78 "CRCW06030000Z0EA" 0603 1131,1110 r0 top
R79 "RR0816Q-22R1-D-34R" 0603 1261,1110 r0 top
R80 "ERJ-3GEY0R00V" 0603 375,1515 r0 top locked
R81 "ERJ-2GE0R00X" 0402 1562,883 r90 top
R82 "RG1608P-102-B-T5" 0603 656,1120 r0 top
R83 "RG1608P-102-B-T5" 0603 656,1040 r0 top
R84 "CRCW06030000Z0EA" 0603 1505,1365 r180 top
R85 "CRCW06031R00FKEA" 0603 1505,1300 r0 top
R86 "ERJ-3GEY0R00V" 0603 375,645 r0 top locked
R87 "ERJ-2GE0R00X" 0402 2189.58,1775.91 r0 top
R88 "CRCW06030000Z0EA" 0603 1131,1045 r0 top
R89 "RR0816Q-22R1-D-34R" 0603 1261,1045 r0 top
R90 "ERJ-2RKF1002X" 0402 1693,1357 r0 top
R91 "ERJ-2GE0R00X" 0402 1512,883 r270 top
R92 "RG1608P-102-B-T5" 0603 956,1010 r0 bottom
R93 "ERJ-2BQFR22X" 0402 1693,1422 r180 top
R94 "RG1608P-203-B-T5" 0603 865,1518 r0 top
R95 "CRCW06031K00FKEA" 0603 1069.5,1521 r180 top
R96 "RG1608P-4990-B-T5" 0603 963,1551 r270 top
R97 "RG1608P-4992-B-T5" 0603 1156,1750 r0 top
R98 "CRCW06030000Z0EA" 0603 1505,1431 r180 top
R99 "ERJ-3RQFR22V" 0603 1244,1289 r0 top
R100 "ERJ-3RQFR22V" 0603 1219.06,1629.94 r0 top
R101 "RG1608P-4992-B-T5" 0603 1054.5,1716 r90 top
R102 "ERJ-2GE0R00X" 0402 2085.58,1774.91 r180 top
R103 "CRCW06030000Z0EA" 0603 3013,2497 r180 bottom
R104 "CRCW06030000Z0EA" 0603 3012,2560 r0 bottom
R105 "ERJ-2RKF1002X" 0402 2169.18,1464.77 r270 top
R106 "ERJ-2RKF1002X" 0402 2022.18,1464.77 r90 top
R107 "ERJ-2RKF1002X" 0402 2071.18,1464.77 r90 top
R108 "ERJ-2RKF1002X" 0402 2187.04,1018.4 r270 top
R109 "ERJ-2RKF1002X" 0402 2040.04,1018.4 r90 top
R110 "ERJ-2RKF1002X" 0402 2089.04,1018.4 r90 top
R111 "ERJ-2RKF1002X" 0402 2138.04,1018.4 r90 top
R112 "ERJ-2RKF1002X" 0402 2039.68,507.27 r90 top
R113 "ERJ-2RKF1002X" 0402 2088.68,507.27 r90 top
R114 "ERJ-2RKF1002X" 0402 2186.68,507.27 r90 top
R115 "ERJ-2RKF1002X" 0402 2137.68,507.27 r90 top
R116 "CRCW08050000Z0EA" 0805_HV 2028.18,2051.77 r0 top
R117 "CRCW08050000Z0EA" 0805_HV 1869.18,2051.77 r180 top
T1 "750313734" Wurth_750313638 2631,2500 r180 top
T2 "750315240" Wurth_750315240 2583,2496 r180 top
TP1 "TP-025-SMT" TP_25MIL-SMT 1596.64,451 r0 top
TP2 "5015" Testpoint_Keystone_Miniature 174.07,2406.86 r270 top
TP3 "5015" Testpoint_Keystone_Miniature 1960.79,2449.35 r90 top
TP4 "5015" Testpoint_Keystone_Miniature 3700,2514 r90 top
TP5 "5015" Testpoint_Keystone_Miniature 3064,2133 r180 top
TP6 "5015" Testpoint_Keystone_Miniature 3681,1462 r90 top
TP7 "5015" Testpoint_Keystone_Miniature 1304,2599 r270 top
TP8 "5015" Testpoint_Keystone_Miniature 930,2115 r180 top
TP9 "5015" Testpoint_Keystone_Miniature 1170,2120 r0 top
TP10 "5015" Testpoint_Keystone_Miniature 935,2835 r180 top
TP11 "5015" Testpoint_Keystone_Miniature 1160,2835 r180 top
TP12 "5015" Testpoint_Keystone_Miniature 2372,2835 r180 top
TP13 "5015" Testpoint_Keystone_Miniature 470,2836 r180 top
TP14 "5015" Testpoint_Keystone_Miniature 2890,2835 r180 top
TP15 "5015" Testpoint_Keystone_Miniature 2795,85 r180 top
TP16 "5015" Testpoint_Keystone_Miniature 3825,1840 r90 top
TP17 "5015" Testpoint_Keystone_Miniature 1743,178 r180 top
TP18 "5015" Testpoint_Keystone_Miniature 525,85 r180 top
TP19 "5015" Testpoint_Keystone_Miniature 2427,86 r180 top
TP20 "TP-025-SMT" TP_25MIL-SMT 2250,2013 r90 top
TP21 "TP-025-SMT" TP_25MIL-SMT 1890,1736 r90 top
TP22 "TP-025-SMT" TP_25MIL-SMT 2212,1726 r90 top locked
U1 "BR24G32FVT-3AGE2" TSOP65P640X120-8N 3045,445 r270 top
U2 "LMK61E2-SIAT" SIA0008B 1045,373 r0 top
U3 "SN65LVDS4RSET" RSE0010A 1450.51,325 r0 top
U4 "SN6505ADBVR" DBV0006A_N 3000,2500 r0 top
U5 "LMZ14203TZ-ADJ/NOPB" TZA07A_V 3423,1965 r270 top
U6 "TPS7A4700RGWR" RGW0020A 425.06,2280.06 r0 top
U7 "TPS7A4700RGWR" RGW0020A 3090,1963.35 r180 bottom
U8 "TPS7A4700RGWR" RGW0020A 1569,2477.27 r0 top
U9 "TPS70918DBVT" DBV0005A_N 902,2488 r270 top
U10 "TPS70918DBVT" DBV0005A_N 1131,2489 r270 top
U11 "ISO7840DW" DW0016B_N 2624,1624 r180 top
U12 "SN74AVC4T245DGVR" DGV0016A_N 2106.18,1602.77 r180 top
U13 "SN74AVC4T245DGVR" DGV0016A_N 2107.04,1156.4 r180 top
U14 "SN74AVC4T245DGVR" DGV0016A_N 2106.68,649.27 r180 top
U19 "ISO7842DWR" DW0016B_N 2624,1155 r180 top
U21 "SN74AHC1G04DBVR" DBV0005A_N 2211.58,1898.91 r90 top
U22 "ISO7840DW" DW0016B_N 2625,685 r0 top
U25 "ISO1541DR" D0008A_N 2624,269 r180 top
U27 "SN74AUP1G80DCKR" DCK0005A_N 2014.71,1887.41 r0 top
U29 "ADS8900BIRGER" RGE0024H 1609.06,1074.94 r270 top
U30 "THS4551IRGTR" RGT0016A 956,1080 r0 top
U31 "REF5050AIDGKT" DGK0008A_N 1679.85,1593.28 r270 top
U32 "REF6041AIDGK" DGK0008A_N 1354.06,1593.28 r270 top
U33 "OPA376AIDBVR" DBV0005A_N 855,1710 r180 top
Y1 "ASTMLPE-125.000MHZ-LJ-E-T" TXC_AU 1700,370 r270 top
ZZ1 "These assemblies are ESD sensitive, ESD precautions shall be observed." AssemblyNote 1803.9,6136.61 r0 top
ZZ2 "These assemblies must be clean and free from flux and all contaminants. Use of no clean flux is not acceptable." AssemblyNote 1803.9,6051.61 r0 top
ZZ3 "These assemblies must comply with workmanship standards IPC-A-610 Class 2, unless otherwise specified." AssemblyNote 1803.9,5976.61 r0 top

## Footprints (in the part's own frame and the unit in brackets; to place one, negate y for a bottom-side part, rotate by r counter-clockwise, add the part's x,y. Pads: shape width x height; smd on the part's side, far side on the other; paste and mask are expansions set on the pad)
0201 [mil]
  rect 16x13 smd: 1(-12.5,0) 2(12.5,0)
0402 [mm] "0402 from SM-752 data"
  rect 0.8x0.6 smd: 1(-0.6,0) 2(0.6,0)
  silkscreen extent -1.22,-0.52 1.22,0.52, body extent -0.55,-0.3 0.55,0.3, height 0.6
0603 [mm] "0603 from SM-752 data"
  rect 1x0.95 smd: 1(-0.8,0) 2(0.8,0)
  silkscreen extent -1.52,-0.69 1.52,0.69, body extent -0.87,-0.47 0.87,0.47, height 1
0603_120 [mm] "0603_120"
  rect 1x1 smd: 1(-0.8,0) 2(0.8,0)
  silkscreen extent -0.1,-0.58 0.1,0.58, body extent -0.87,-0.48 0.87,0.48, height 1.2
0805 [mm] "0805 from SM-752 data"
  rect 1.3x1.5 smd: 1(-0.85,0) 2(0.85,0)
  silkscreen extent -1.72,-0.97 1.72,0.97, body extent -1.1,-0.72 1.1,0.72, height 1.45
0805_HV [mil] "0805 with 30mil clearance between pads"
  rect 50x63 smd: 1(-40,0) 2(40,0)
  silkscreen extent -74,-40 74,40, body extent -43,-29 43,29, height 57
1206 [mm] "1206 from SM-752 data"
  rect 1.3x1.85 smd: 1(-1.45,0) 2(1.45,0)
  silkscreen extent -2.4,-1.21 2.4,1.21, body extent -1.7,-0.9 1.7,0.9, height 1.35
1206_190 [mm] "1206_190"
  rect 1.1x1.6 smd: 1(-1.7,0) 2(1.7,0)
  silkscreen extent -0.9,-1 0.9,1, body extent -1.75,-0.95 1.75,0.95, height 1.9
1210 [mm] "1210 from SM-752 data"
  rect 1.3x2.7 smd: 1(-1.45,0) 2(1.45,0)
  silkscreen extent -2.32,-1.57 2.32,1.57, body extent -1.7,-1.35 1.7,1.35, height 1.35
1210_280 [mm] "SMD, 2-Leads, Body 3.6x2.8mm, Height 2.8mm"
  rect 1.1x2.2 smd: 1(-1.65,0) 2(1.65,0)
  silkscreen extent -0.84,-1.4 0.84,1.4, body extent -1.8,-1.4 1.8,1.4, height 2.8
7343-43 [mm] "Medium density IPC based on Kemet T495 series"
  rect 2.55x2.45 smd: 1(-3.025,0) 2(3.025,0)
  silkscreen extent -4.56,-2.3 3.8,2.3, body extent -3.8,-2.3 3.8,2.3, height 4.3
691213510002 [mm] "Serie 2135 - 5.08 mm _ 2 pins"
  rect 1.8x1.8 hole 1.3: 1(-2.54,0)
  round 1.8 hole 1.3: 2(2.54,0)
  silkscreen extent -5.6,-4.05 5.6,4.05, body extent -5.68,-4 5.68,4.1, height 10.1
AssemblyNote [mil] "Assembly Note"
D0008A_N [mm] "SOIC, 8-Leads, Body 4.9x3.9mm, Pitch 1.27mm, IPC Medium Density"
  oval 1.45x0.6 smd: 1(-2.725,1.905) 2(-2.725,0.635) 3(-2.725,-0.635) 4(-2.725,-1.905) 5(2.725,-1.905) 6(2.725,-0.635) 7(2.725,0.635) 8(2.725,1.905)
  silkscreen extent -3.3,-2.5 0.9,2.5, body extent -3,-2.45 3,2.45, height 1.63
DBV0005A_N [mm]
  rrect17% 1x0.6 smd: 1(-1.375,0.95) 2(-1.375,0) 3(-1.375,-0.95) 4(1.375,-0.95) 5(1.375,0.95)
  silkscreen extent -1.63,-1.55 0.38,1.55, body extent -1.42,-1.46 1.42,1.46, height 1.09
DBV0006A_N [mm] "SOT23, 6-Leads, Body 2.9x1.6mm, Pitch 0.95mm, Lead Span 2.8mm, IPC Medium Density"
  rrect17% 1x0.6 smd: 1(-1.375,0.95) 2(-1.375,0) 3(-1.375,-0.95) 4(1.375,-0.95) 5(1.375,0) 6(1.375,0.95)
  silkscreen extent -1.68,-1.55 0.5,1.55, body extent -1.42,-1.46 1.42,1.46, height 1.12
DCK0005A_N [mm] "SOT353, 5-Leads, Body 2x1.3mm, Pitch 0.65mm, Lead Span 2.1mm, IPC Medium Density"
  rrect25% 0.85x0.4 smd: 1(-1.125,0.65) 2(-1.125,0) 3(-1.125,-0.65) 4(1.125,-0.65) 5(1.125,0.65)
  silkscreen extent -1.48,-1.02 0.55,1.1, body extent -1.14,-1 1.14,1, height 0.95
DGK0008A_N [mm] "TSOP, 8-Leads, Body 3x3mm, Pitch 0.65mm, IPC Medium Density"
  oval 1.35x0.45 smd: 1(-2.225,0.975) 2(-2.225,0.325) 3(-2.225,-0.325) 4(-2.225,-0.975) 5(2.225,-0.975) 6(2.225,-0.325) 7(2.225,0.325) 8(2.225,0.975)
  silkscreen extent -2.75,-1.55 0.95,1.55, body extent -2.45,-1.5 2.45,1.5, height 0.96
DGV0016A_N [mm] "TSSOP, 16-Leads, Body 3.6x4.4mm, Pitch 0.4mm, IPC Medium Density"
  oval 1.4x0.2 smd: 1(-2.95,1.4) 2(-2.95,1) 3(-2.95,0.6) 4(-2.95,0.2) 5(-2.95,-0.2) 6(-2.95,-0.6) 7(-2.95,-1) 8(-2.95,-1.4) 9(2.95,-1.4) 10(2.95,-1) 11(2.95,-0.6) 12(2.95,-0.2) 13(2.95,0.2) 14(2.95,0.6) 15(2.95,1) 16(2.95,1.4)
  silkscreen extent -3.45,-1.85 1.85,1.85, body extent -3.21,-1.8 3.21,1.8, height 1.2
DW0016B_N [mm] "SOIC, 16-Leads, Body 10.5x7.6mm, Pitch 1.27mm, IPC Medium Density"
  rrect17% 1.9x0.6 smd: 1(-4.75,4.445) 2(-4.75,3.175) 3(-4.75,1.905) 4(-4.75,0.635) 5(-4.75,-0.635) 6(-4.75,-1.905) 7(-4.75,-3.175) 8(-4.75,-4.445) 9(4.75,-4.445) 10(4.75,-3.175) 11(4.75,-1.905) 12(4.75,-0.635) 13(4.75,0.635) 14(4.75,1.905) 15(4.75,3.175) 16(4.75,4.445)
  silkscreen extent -5.6,-5.25 3.4,5.25, body extent -5.17,-5.15 5.17,5.15, height 2.59
ESD_Overlay_small [mil]
  silkscreen extent -62,-48 64,61
FCC_disclaimer [mil]
Fiducial10-20 [mm]
  round 1 smd mask+0.5: 1(0,0)
  Top Layer keep-out circle w1.178: c0,0 r0.5
JOHNSON_142-0701-801#1 [mil] "Johnson Components recommended land pattern"
  rect 90x200 smd: 1(0,0)
  round 38 hole 18: 2(-172.5,-135) 3(172.5,-135)
  rect 95x200 smd: 2(-172.5,0) 3(172.5,0)
  rect 95x200 smd far side: 4(-172.5,0) 5(172.5,0)
  Top Layer lines w18: -172.5,0 -172.5,-53.5 -172.5,-135 ; 172.5,0 172.5,-53.5 172.5,-135
  Bottom Layer lines w18: -172.5,0 -172.5,-51.5 -172.5,-54.5 -172.5,-135 ; 172.5,0 172.5,-51.5 172.5,-54.5 172.5,-135
  silkscreen extent -235,-170 235,100, body extent -190,-92 190,480, height 165
JOHNSON_142-0701-801#2 [mil] "Johnson Components recommended land pattern"
  rect 90x200 smd: 1(0,0)
  round 38 hole 18: 2(-172.5,-135) 3(172.5,-135)
  rect 95x200 smd: 2(-172.5,0) 3(172.5,0)
  rect 95x200 smd far side: 4(-172.5,0) 5(172.5,0)
  Top Layer lines w18: -172.5,0 -172.5,-53.5 -172.5,-135 ; 172.5,0 172.5,-53.5 172.5,-135
  Bottom Layer lines w18: -172.5,0 -172.5,-51.5 -172.5,-135 ; 172.5,0 172.5,-51.5 172.5,-54.5 172.5,-135
  silkscreen extent -235,-170 235,100, body extent -190,-92 190,480, height 165
Keystone_1902C [mil] "Hex Standoff, 4-40 threaded, nylon"
  round 1 on Mech4: 0(0,0)
  body extent -145,-126 146,126, height 501
Molex_87898-0204 [mm] "Header, 2.54 mm, 2x1, R/A, SMT"
  rect 1.27x2.96 smd: 1(-1.27,1.8) 2(1.27,-1.8)
  silkscreen extent -2.54,-1.27 2.54,1.27, body extent -2.54,-2.4 2.54,2.4, height 9.65
"NY PMS 440 0025 PH" [mm] "4-40 nylon screw and mounting hole"
  round 8 hole 3.2: 1(0,0)
  body extent -3.3,-3.3 3.3,3.3, height 2.69
Pb-Free_Overlay_Small [mil]
  silkscreen extent -46,-46 46,46
RGE0024H [mm] "QFN, 24-Leads, Body 4x4mm, Pitch 0.5mm, Thermal Pad 2.7x2.7mm, TI Recommended"
  oval 0.6x0.24 smd: 1(-1.9,1.25) 2(-1.9,0.75) 3(-1.9,0.25) 4(-1.9,-0.25) 5(-1.9,-0.75) 6(-1.9,-1.25) 13(1.9,-1.25) 14(1.9,-0.75) 15(1.9,-0.25) 16(1.9,0.25) 17(1.9,0.75) 18(1.9,1.25)
  oval 0.24x0.6 smd: 7(-1.25,-1.9) 8(-0.75,-1.9) 9(-0.25,-1.9) 10(0.25,-1.9) 11(0.75,-1.9) 12(1.25,-1.9) 19(1.25,1.9) 20(0.75,1.9) 21(0.25,1.9) 22(-0.25,1.9) 23(-0.75,1.9) 24(-1.25,1.9)
  rect 2.7x2.7 smd paste-1.35: 25(0,0)
  silkscreen extent -2.22,-2.22 2.22,2.22, body extent -2.07,-2.07 2.07,2.07, height 1.01
RGT0016A [mm] "QFN, 16-Leads, Body 3x3mm, Pitch 0.5mm, Thermal Pad 1.45x1.45mm, TI Recommended"
  rrect42% 0.6x0.24 smd: 1(-1.4,0.75) 2(-1.4,0.25) 3(-1.4,-0.25) 4(-1.4,-0.75) 9(1.4,-0.75) 10(1.4,-0.25) 11(1.4,0.25) 12(1.4,0.75)
  rrect42% 0.24x0.6 smd: 5(-0.75,-1.4) 6(-0.25,-1.4) 7(0.25,-1.4) 8(0.75,-1.4) 13(0.75,1.4) 14(0.25,1.4) 15(-0.25,1.4) 16(-0.75,1.4)
  rrect7% 1.45x1.45 smd paste-0.725: 17(0,0)
  silkscreen extent -1.72,-1.73 1.72,1.73, body extent -1.57,-1.57 1.58,1.58, height 1.01
RGW0020A [mm] "QFN, 20-Leads, Body 5x5mm, Pitch 0.65mm, Thermal Pad 3.15x3.15mm, TI Recommended"
  oval 0.75x0.3 smd: 1(-2.325,1.3) 2(-2.325,0.65) 3(-2.325,0) 4(-2.325,-0.65) 5(-2.325,-1.3) 11(2.325,-1.3) 12(2.325,-0.65) 13(2.325,0) 14(2.325,0.65) 15(2.325,1.3)
  oval 0.3x0.75 smd: 6(-1.3,-2.325) 7(-0.65,-2.325) 8(0,-2.325) 9(0.65,-2.325) 10(1.3,-2.325) 16(1.3,2.325) 17(0.65,2.325) 18(0,2.325) 19(-0.65,2.325) 20(-1.3,2.325)
  rect 3.15x3.15 smd paste-1.575: 21(0,0)
  silkscreen extent -2.73,-2.73 2.73,2.73, body extent -2.58,-2.57 2.57,2.58, height 1.01
RSE0010A [mm] "QFN, 10-Leads, Body 1.5x2mm, Pitch 0.5mm, TI Recommended"
  rect 0.55x0.2 smd: 1(-0.675,0.75) 2(-0.675,0.25) 3(-0.675,-0.25) 4(-0.675,-0.75) 6(0.675,-0.75) 7(0.675,-0.25) 8(0.675,0.25) 9(0.675,0.75)
  rect 0.3x0.6 smd: 5(0,-0.9) 10(0,0.9)
  silkscreen extent -1.07,-1.17 0.77,1.18, body extent -0.77,-1.02 0.78,1.03, height 0.61
SAMTEC_QTH-030-01-X-D-A [mil] "Header (Shrouded), 19.7mil, 30x2, SMT"
  rect 12x57 smd: 1(-285.7,121.5) 2(-285.7,-121.5) 3(-266,121.5) 4(-266,-121.5) 5(-246.3,121.5) 6(-246.3,-121.5) 7(-226.6,121.5) 8(-226.6,-121.5) 9(-206.9,121.5) 10(-206.9,-121.5) 11(-187.2,121.5) 12(-187.2,-121.5) 13(-167.5,121.5) 14(-167.5,-121.5) 15(-147.8,121.5) 16(-147.8,-121.5) 17(-128.1,121.5) 18(-128.1,-121.5) 19(-108.4,121.5) 20(-108.4,-121.5) 21(-88.7,121.5) 22(-88.7,-121.5) 23(-69,121.5) 24(-69,-121.5) 25(-49.3,121.5) 26(-49.3,-121.5) 27(-29.6,121.5) 28(-29.6,-121.5) 29(-9.9,121.5) 30(-9.9,-121.5) 31(9.8,121.5) 32(9.8,-121.5) 33(29.5,121.5) 34(29.5,-121.5) 35(49.2,121.5) 36(49.2,-121.5) 37(68.9,121.5) 38(68.9,-121.5) 39(88.6,121.5) 40(88.6,-121.5) 41(108.3,121.5) 42(108.3,-121.5) 43(128,121.5) 44(128,-121.5) 45(147.7,121.5) 46(147.7,-121.5) 47(167.4,121.5) 48(167.4,-121.5) 49(187.1,121.5) 50(187.1,-121.5) 51(206.8,121.5) 52(206.8,-121.5) 53(226.5,121.5) 54(226.5,-121.5) 55(246.2,121.5) 56(246.2,-121.5) 57(265.9,121.5) 58(265.9,-121.5) 59(285.6,121.5) 60(285.6,-121.5)
  round 40 hole 40 unplated paste+0 mask+5: MH1(-364,80)
  round 40 hole 40 unplated mask+10: MH2(364,80)
  rect 100x25 smd: MP1(-332.7,0) MP4(332.3,0)
  rect 185x25 smd: MP2(-125.2,0) MP3(124.8,0)
  silkscreen extent -394,-118 394,131, body extent -394,-140 394,140, height 170
SIA0008B [mm] "SIP 8-Leads, Body 5x7mm"
  rrect17% 1x0.6 on Top Paste: 1(-1.85,2.14) 1(-1.85,2.94) 2(-1.85,-0.4) 2(-1.85,0.4) 3(-1.85,-2.94) 3(-1.85,-2.14) 4(1.85,-2.94) 4(1.85,-2.14) 5(1.85,-0.4) 5(1.85,0.4) 6(1.85,2.14) 6(1.85,2.94)
  rrect10% 1x1.4 smd paste-0.5: 1(-1.85,2.54) 2(-1.85,0) 3(-1.85,-2.54) 4(1.85,-2.54) 5(1.85,0) 6(1.85,2.54)
  rrect12% 0.8x0.8 smd: 7(0,2.865) 8(0,-2.865)
  silkscreen extent -2.64,-3.63 2.64,3.63, body extent -2.56,-3.56 2.56,3.56, height 1.13
SMC [mm] "DO-214-AB/SMC; 2 C-Bend Leads; Body 7.9 x 5.9 mm, inc. leads (LxW)"
  rect 2.4x3.3 smd: 1(-3.475,0) 2(3.475,0)
  silkscreen extent -5.07,-2.05 5.43,2.05
SOD-123 [mm] "On Semi recommended land pattern"
  rect 0.915x1.22 smd: 1(-1.637,0) 2(1.637,0)
  silkscreen extent -2.74,-1.17 2.03,1.17, body extent -1.93,-0.9 1.93,0.9, height 1.35
Testpoint_Keystone_Miniature [mil] "Miniature SMT test point"
  rect 135x70 smd: 1(0,0)
  silkscreen extent -78,-46 78,45, body extent -52,-20 52,20, height 61
TP_25MIL-SMT [mil]
  round 25 smd mask-2.5: 1(0,0)
TSOP65P640X120-8N [mm] "TSOP, 8-Leads, Body 3.1x4.5mm (max), Pitch 0.65mm, IPC Medium Density"
  oval 1.55x0.35 smd mask+0.08: 1(-2.875,0.975) 2(-2.875,0.325) 3(-2.875,-0.325) 4(-2.875,-0.975) 5(2.875,-0.975) 6(2.875,-0.325) 7(2.875,0.325) 8(2.875,0.975)
  silkscreen extent -1.7,-1.55 1.7,1.55, body extent -2.25,-1.55 2.25,1.55, height 1.21
TXC_AU [mm] "SMD, 4-Leads, Body 3.2x2.5mm"
  rect 1.2x1.4 smd: 1(-0.85,1.1) 2(-0.85,-1.1) 3(0.85,-1.1) 4(0.85,1.1)
  silkscreen extent -1.84,-0.1 1.3,1.21, body extent -1.3,-1.65 1.3,1.65, height 1.11
TZA07A_V [mm] "D2-PAK, 8-Leads, Body 9.9x10.2mm, Pitch 1.27mm, Lead Span 13.8mm, NSC Recommended"
  rect 2.41x0.89 smd: 1(-5.35,3.81) 2(-5.35,2.54) 3(-5.35,1.27) 4(-5.35,0) 5(-5.35,-1.27) 6(-5.35,-2.54) 7(-5.35,-3.81)
  rect 8.54x5.35 smd: 8(2.28,0)
  silkscreen extent -5.47,-5.15 -2.7,5.15, body extent -2.55,-5.2 7.55,5.2, height 4.67
WL-SMCW_RED [mm] "WURTH"
  rect 0.8x0.8 smd: 1(-0.8,0) 2(0.8,0)
  silkscreen extent -1.9,-0.8 1.2,0.8, body extent -0.85,-0.45 0.85,0.45, height 0.8
Wurth_750313638 [mm] "SMD, 6-Leads, Body 8x9.14mm, Pitch 3.05mm"
  rect 1.9x1.14 smd: 1(-5.655,3.05) 2(-5.655,0) 3(-5.655,-3.05) 4(5.655,-3.05) 5(5.655,0) 6(5.655,3.05)
  silkscreen extent -4,-4.57 4,4.87, body extent -6.35,-4.57 6.35,4.57, height 7.62
Wurth_750315240 [mm] "SMD, 6-Leads, Body 10.41x12.32mm"
  rect 1.335x1.215 smd: 1(-6.87,3.81) 2(-6.87,0) 3(-6.87,-3.81) 4(6.87,-3.81) 5(6.87,0) 6(6.87,3.81)
  silkscreen extent -5.21,-6.16 5.21,6.5, body extent -7.43,-6.16 7.43,6.16, height 11.06
WURTH_61300211121 [mm] "Header, 2.54mm, 2x1, TH"
  rect 1.65x1.65 hole 1.15: 1(-1.27,0)
  round 1.65 hole 1.15: 2(1.27,0)
  silkscreen extent -2.54,-1.27 2.54,1.6, body extent -2.54,-1.27 2.54,1.27, height 8.54
WURTH_61300311121 [mm] "Header, 2.54mm, 3x1, TH"
  rect 1.65x1.65 hole 1.15: 1(-2.54,0)
  round 1.65 hole 1.15: 2(0,0) 3(2.54,0)
  silkscreen extent -3.81,-1.27 3.81,1.6, body extent -3.81,-1.27 3.81,1.27, height 8.54
Wurth_WA-SMSI [mm] "ROUND STANDOFF M3 STEEL 5MM"
  round 0 hole 4.4 unplated: ""(0,0)
  Top Layer region: -3.711,0 -3.666,0.581 -3.53,1.147 -3.307,1.685 -3.003,2.182 -2.624,2.624 -2.182,3.003 -1.685,3.307 -1.147,3.53 -0.581,3.666 0,3.711 0.581,3.666 1.147,3.53 1.685,3.307 2.182,3.003 2.624,2.624 3.003,2.182 3.307,1.685 3.53,1.147 3.666,0.581 3.711,0 3.7,0 2.466,0 2.418,0.481 2.278,0.944 2.05,1.37 1.744,1.744 1.37,2.05 0.944,2.278 0.481,2.418 0,2.466 -0.481,2.418 -0.944,2.278 -1.37,2.05 -1.744,1.744 -2.05,1.37 -2.278,0.944 -2.418,0.481 -2.466,0 -2.454,0
  Top Layer region: -3.711,0 -3.666,-0.581 -3.53,-1.147 -3.307,-1.685 -3.003,-2.182 -2.624,-2.624 -2.182,-3.003 -1.685,-3.307 -1.147,-3.53 -0.581,-3.666 0,-3.711 0.581,-3.666 1.147,-3.53 1.685,-3.307 2.182,-3.003 2.624,-2.624 3.003,-2.182 3.307,-1.685 3.53,-1.147 3.666,-0.581 3.711,0 3.7,0 2.466,0 2.418,-0.481 2.278,-0.944 2.05,-1.37 1.744,-1.744 1.37,-2.05 0.944,-2.278 0.481,-2.418 0,-2.466 -0.481,-2.418 -0.944,-2.278 -1.37,-2.05 -1.744,-1.744 -2.05,-1.37 -2.278,-0.944 -2.418,-0.481 -2.466,0 -2.454,0
  silkscreen extent -4.1,-4.1 4.1,4.1, body extent -2.99,-2.98 2.99,3, height 5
